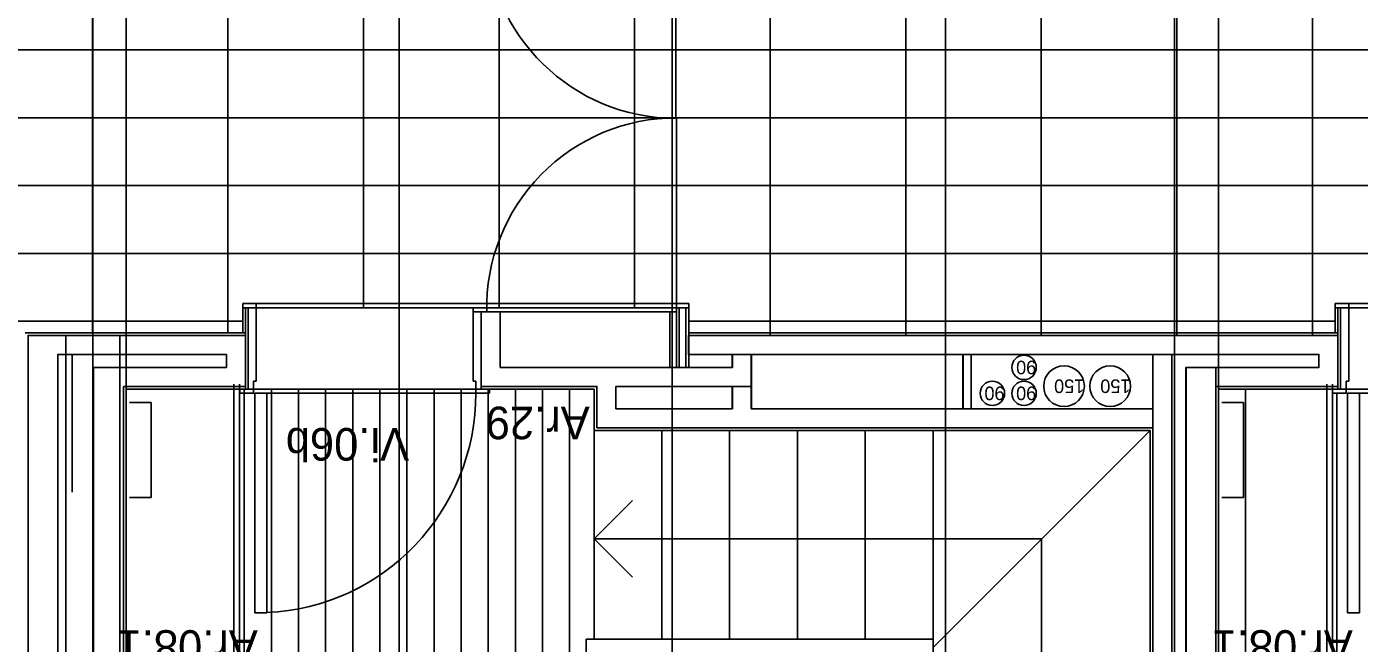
# Model space of a CAD drawing. Extents: x 1248 to 1356, y -443 to -224.
# Drawn here: x 1299.176 to 1304.091, y -239.861 to -237.588 of the extents above; entities that cross this region are included whole.
import ezdxf

# ---------------------------------------------------------------- set-up
doc = ezdxf.new("R2010")
doc.units = 0
for name, color, linetype in [('corte', 7, 'Continuous'), ('estereoctomias', 7, 'Continuous'), ('Level 1', 7, 'Continuous'), ('Level 10', 7, 'Continuous'), ('Level 13', 7, 'Continuous'), ('Level 2', 7, 'Continuous'), ('Level 4', 7, 'Continuous'), ('Level 40', 7, 'Continuous'), ('Level 41', 7, 'Continuous'), ('mob-fixo', 7, 'Continuous'), ('revestimentos', 7, 'Continuous'), ('vermelhos-cont', 7, 'Continuous'), ('vermelhos-tracej', 7, 'Continuous')]:
    doc.layers.add(name, color=color, linetype=linetype)

msp = doc.modelspace()

# ---------------------------------------------------------------- linework, layer by layer
at = {"layer": 'corte'}
for p, q in [((1300.8527, -238.914), (1300.8527, -238.639)), ((1300.9227, -238.844), (1300.9227, -238.639)), ((1299.3208, -238.7263), (1299.519, -238.7263)), ((1302.629, -238.7963), (1302.629, -238.9963)), ((1302.659, -238.7963), (1302.659, -238.9963)), ((1303.3294, -238.9963), (1303.3294, -238.7963)), ((1303.3994, -242.7713), (1303.3994, -238.7963)), ((1299.4227, -238.844), (1299.4227, -243.794)), ((1300.9227, -238.844), (1301.7783, -238.844)), ((1303.4523, -238.844), (1303.4523, -242.7713)), ((1303.5623, -243.914), (1303.5623, -238.844)), ((1299.5327, -243.914), (1299.5327, -238.914)), ((1300.8527, -238.914), (1301.2787, -238.914)), ((1301.3487, -238.914), (1301.7783, -238.914)), ((1301.3487, -238.9963), (1301.7783, -238.9963)), ((1301.8483, -238.9963), (1303.3294, -238.9963)), ((1301.8483, -238.9963), (1303.2742, -238.9963)), ((1303.3294, -240.6863), (1303.3294, -239.0763))]:
    msp.add_line(p, q, dxfattribs=at)
msp.add_lwpolyline([(1299.519, -238.7263), (1299.519, -243.774), (1299.3208, -243.774), (1299.3208, -238.7263)], dxfattribs=at)
at = {"layer": 'estereoctomias'}
for p, q in [((1300.8227, -238.624), (1300.0227, -238.624)), ((1304.8523, -238.624), (1304.0523, -238.624))]:
    msp.add_line(p, q, dxfattribs=at)
for points in [[(1303.3298, -239.0663), (1301.2791, -239.0663), (1301.2791, -238.914), (1300.8527, -238.914), (1300.8527, -238.639), (1300.9227, -238.639), (1300.9227, -238.844), (1301.7791, -238.844), (1301.7791, -238.7963), (1301.8491, -238.7963), (1301.8491, -238.914), (1301.3491, -238.914), (1301.3491, -238.9963), (1301.7791, -238.9963), (1301.7791, -238.914), (1301.8491, -238.914), (1301.8491, -238.9963), (1302.6298, -238.9963), (1302.6298, -238.7963), (1302.6598, -238.7963), (1302.6598, -238.9963), (1303.3298, -238.9963)], [(1299.5327, -238.914), (1299.9827, -238.914), (1299.9827, -238.7263), (1299.519, -238.7263), (1299.519, -238.7963), (1299.9127, -238.7963), (1299.9127, -238.844), (1299.519, -238.844), (1299.519, -243.774), (1299.4227, -243.774), (1299.4227, -243.804), (1299.2908, -243.804), (1299.2908, -238.7963), (1299.3208, -238.7963), (1299.3208, -238.7263), (1299.1808, -238.7263), (1299.1808, -243.914), (1299.519, -243.914), (1299.5327, -243.914), (1299.5304, -240.9963), (1299.9404, -240.9963), (1299.9404, -240.9263), (1299.5327, -240.9263)], [(1301.6173, -238.7263), (1301.6173, -238.7963), (1303.9423, -238.7963), (1303.9423, -238.844), (1303.5623, -238.844), (1303.5623, -238.914), (1304.0123, -238.914), (1304.0123, -238.7263)], [(1303.3994, -242.7713), (1303.3294, -242.7713), (1303.3294, -240.7563), (1301.2594, -240.7563), (1301.2594, -240.6863), (1303.3294, -240.6863), (1303.3294, -238.7963), (1303.5738, -238.7963), (1303.3994, -238.7963), (1303.3994, -242.7713)], [(1303.4519, -242.7713), (1303.5619, -242.7713), (1303.5619, -240.9963), (1303.9719, -240.9963), (1303.9719, -240.9263), (1303.5619, -240.9263), (1303.5619, -238.844), (1303.4519, -238.844)]]:
    msp.add_lwpolyline(points, close=True, dxfattribs=at)
at = {"layer": 'Level 1'}
for p, q in [((1300.9227, -238.639), (1300.8527, -238.639)), ((1299.1808, -238.7263), (1299.9827, -238.7263)), ((1299.1808, -243.914), (1299.1808, -238.7263)), ((1299.9827, -238.924), (1299.9827, -238.7163)), ((1301.6177, -238.7263), (1301.6177, -238.7963)), ((1303.5742, -238.7263), (1301.6177, -238.7263)), ((1303.3442, -238.7263), (1304.0123, -238.7263)), ((1304.0123, -238.924), (1304.0123, -238.7163)), ((1299.2908, -238.7963), (1299.9127, -238.7963)), ((1299.2908, -243.794), (1299.2908, -238.7963)), ((1299.3433, -239.304), (1299.3433, -238.7963)), ((1299.9127, -238.844), (1299.9127, -238.7963)), ((1301.7783, -238.7963), (1301.6177, -238.7963)), ((1301.7783, -238.7963), (1301.7783, -238.844)), ((1301.8483, -238.7963), (1301.8483, -238.9963)), ((1303.3294, -238.7963), (1301.8483, -238.7963)), ((1303.3994, -238.7963), (1303.9423, -238.7963)), ((1303.9423, -238.844), (1303.9423, -238.7963)), ((1299.4227, -238.844), (1299.9127, -238.844)), ((1303.4523, -238.844), (1303.9423, -238.844)), ((1299.5327, -238.914), (1299.9827, -238.914)), ((1301.2787, -238.914), (1301.2787, -239.0663)), ((1301.3487, -238.914), (1301.3487, -238.9963)), ((1301.7783, -238.914), (1301.7783, -238.9963)), ((1303.5623, -238.914), (1304.0123, -238.914)), ((1303.3294, -239.0663), (1301.2787, -239.0663))]:
    msp.add_line(p, q, dxfattribs=at)
at = {"layer": 'Level 10'}
for p, q in [((1299.4183, -237.1163), (1299.4183, -238.7163)), ((1299.9183, -237.1163), (1299.9183, -238.7163)), ((1301.9183, -237.1163), (1301.9183, -238.724)), ((1302.4183, -237.1163), (1302.4183, -238.724)), ((1302.9183, -237.1163), (1302.9183, -238.724)), ((1303.4183, -237.1163), (1303.4183, -238.724)), ((1303.9183, -237.1163), (1303.9183, -238.724)), ((1300.4183, -237.2259), (1300.4183, -238.624)), ((1300.9183, -237.2259), (1300.9183, -238.624)), ((1301.4183, -237.2259), (1301.4183, -238.624)), ((1299.1415, -237.674), (1318.1944, -237.674)), ((1299.1415, -237.924), (1318.1944, -237.924)), ((1299.1415, -238.174), (1318.1944, -238.174)), ((1296.6333, -238.424), (1309.5183, -238.424)), ((1299.1231, -238.674), (1299.9727, -238.674)), ((1301.6177, -238.674), (1304.0023, -238.674)), ((1299.9785, -240.9713), (1299.9785, -238.924)), ((1300.8327, -238.924), (1300.0027, -238.924)), ((1300.0785, -243.574), (1300.0785, -238.924)), ((1300.1785, -243.574), (1300.1785, -238.924)), ((1300.2785, -243.574), (1300.2785, -238.924)), ((1300.3785, -243.574), (1300.3785, -238.924)), ((1300.4785, -243.574), (1300.4785, -238.924)), ((1300.5785, -243.574), (1300.5785, -238.924)), ((1300.6785, -243.574), (1300.6785, -238.924)), ((1300.7785, -243.574), (1300.7785, -238.924)), ((1300.8785, -243.574), (1300.8785, -238.924)), ((1300.9785, -243.574), (1300.9785, -238.924)), ((1301.0785, -243.574), (1301.0785, -238.924)), ((1301.1785, -240.7663), (1301.1785, -238.924)), ((1304.0081, -240.9713), (1304.0081, -238.939)), ((1304.8623, -238.924), (1304.0323, -238.924))]:
    msp.add_line(p, q, dxfattribs=at)
at = {"layer": 'Level 13'}
for p, q in [((1299.9727, -238.609), (1299.9727, -238.7163)), ((1300.0227, -238.609), (1299.9727, -238.609)), ((1299.9727, -238.624), (1300.0227, -238.624)), ((1299.9827, -238.7163), (1299.9827, -238.624)), ((1299.9927, -238.924), (1299.9927, -238.624)), ((1300.0227, -238.624), (1300.0227, -238.609)), ((1300.0227, -238.895), (1300.0227, -238.624)), ((1300.8227, -238.639), (1300.8227, -238.624)), ((1300.8727, -238.624), (1300.8227, -238.624)), ((1300.8227, -238.639), (1300.8227, -238.895)), ((1301.5727, -238.639), (1300.8227, -238.639)), ((1300.8527, -238.924), (1300.8527, -238.639)), ((1301.5727, -238.624), (1300.8627, -238.624)), ((1301.5727, -238.624), (1300.8627, -238.624)), ((1301.5727, -238.624), (1300.8727, -238.624)), ((1300.8727, -238.639), (1300.8727, -238.624)), ((1301.5727, -238.624), (1301.5727, -238.609)), ((1301.5727, -238.609), (1301.6177, -238.609)), ((1301.5727, -238.639), (1301.5727, -238.624)), ((1301.5727, -238.624), (1301.6177, -238.624)), ((1301.5727, -238.844), (1301.5727, -238.624)), ((1301.5827, -238.624), (1301.5827, -238.844)), ((1301.6077, -238.624), (1301.6077, -238.844)), ((1301.6177, -238.624), (1301.6177, -238.609)), ((1301.6177, -238.644), (1301.6177, -238.624)), ((1301.6177, -238.644), (1301.6177, -238.844)), ((1304.0023, -238.609), (1304.0023, -238.7163)), ((1304.0523, -238.609), (1304.0023, -238.609)), ((1304.0023, -238.624), (1304.0523, -238.624)), ((1304.0123, -238.7163), (1304.0123, -238.624)), ((1304.0223, -238.924), (1304.0223, -238.624)), ((1304.0523, -238.624), (1304.0523, -238.609)), ((1304.0523, -238.895), (1304.0523, -238.624)), ((1299.9404, -241.0063), (1299.9404, -238.9056)), ((1299.9604, -241.0063), (1299.9604, -238.9056)), ((1300.0227, -238.895), (1300.0127, -238.895)), ((1300.0127, -238.895), (1300.0127, -238.924)), ((1300.0177, -239.749), (1300.0177, -238.939)), ((1300.0177, -238.939), (1300.0617, -238.939)), ((1300.0617, -238.939), (1300.0617, -239.749)), ((1300.8227, -238.895), (1300.8327, -238.895)), ((1300.8327, -238.895), (1300.8327, -238.924)), ((1303.9719, -240.9163), (1303.9719, -238.9056)), ((1303.9919, -241.0063), (1303.9919, -238.9056)), ((1304.0523, -238.895), (1304.0423, -238.895)), ((1304.0423, -238.895), (1304.0423, -238.924)), ((1304.0473, -239.749), (1304.0473, -238.939)), ((1304.0473, -238.939), (1304.0913, -238.939)), ((1304.0913, -238.939), (1304.0913, -239.749)), ((1300.0617, -239.749), (1300.0177, -239.749)), ((1304.0913, -239.749), (1304.0473, -239.749))]:
    msp.add_line(p, q, dxfattribs=at)
for points in [[(1299.9627, -238.939), (1300.0127, -238.939), (1300.0127, -238.924), (1299.9627, -238.924)], [(1300.8827, -238.939), (1300.8327, -238.939), (1300.8327, -238.924), (1300.8827, -238.924)], [(1303.9923, -238.939), (1304.0423, -238.939), (1304.0423, -238.924), (1303.9923, -238.924)]]:
    msp.add_lwpolyline(points, close=True, dxfattribs=at)
at = {"layer": 'Level 2'}
for p, q in [((1301.2687, -239.0763), (1301.2687, -239.8463)), ((1301.5187, -239.0763), (1301.5187, -239.8463)), ((1301.7687, -239.0763), (1301.7687, -239.8463)), ((1302.0187, -239.0763), (1302.0187, -239.8463)), ((1302.2687, -239.0763), (1302.2687, -239.8463)), ((1302.5194, -239.0763), (1302.5194, -239.8463)), ((1302.5194, -239.8763), (1303.3194, -239.0763)), ((1301.4101, -239.3349), (1301.2687, -239.4763)), ((1302.9194, -239.4763), (1301.2687, -239.4763)), ((1301.4101, -239.6177), (1301.2687, -239.4763)), ((1302.9194, -239.4763), (1302.9194, -240.2763)), ((1302.5194, -239.8463), (1301.2394, -239.8463)), ((1301.2394, -240.6763), (1301.2394, -239.8463)), ((1302.5194, -239.9063), (1302.5194, -239.8463))]:
    msp.add_line(p, q, dxfattribs=at)
at = {"layer": 'Level 4'}
for p, q in [((1301.5704, -237.2259), (1301.5704, -237.9259)), ((1301.5727, -238.624), (1301.5727, -237.924)), ((1300.0227, -238.609), (1301.5727, -238.609)), ((1301.5477, -238.844), (1301.5477, -238.639)), ((1304.0523, -238.609), (1305.6023, -238.609)), ((1300.8327, -238.939), (1300.0617, -238.939)), ((1304.8623, -238.939), (1304.0913, -238.939)), ((1299.5546, -238.974), (1299.6346, -238.974)), ((1299.6346, -239.324), (1299.6346, -238.974)), ((1303.5842, -238.974), (1303.6642, -238.974)), ((1303.6642, -239.324), (1303.6642, -238.974)), ((1299.5546, -239.324), (1299.6346, -239.324)), ((1303.5842, -239.324), (1303.6642, -239.324))]:
    msp.add_line(p, q, dxfattribs=at)
for centre, start, end in [((1301.5704, -237.2259), 181.2279, 270), ((1301.5727, -238.624), 90, 181.2279)]:
    msp.add_arc(centre, 0.7, start, end, dxfattribs=at)
msp.add_ellipse((1300.0267, -238.939), major_axis=(0, -0.81), ratio=0.995105, start_param=0.043492, end_param=1.570796, dxfattribs=at)
at = {"layer": 'Level 41'}
for centre, radius in [((1302.8547, -238.8443), 0.045), ((1303.002, -238.9135), 0.075), ((1303.1722, -238.9135), 0.075), ((1302.7379, -238.9397), 0.045), ((1302.8547, -238.9397), 0.045)]:
    msp.add_circle(centre, radius, dxfattribs=at)
at = {"layer": 'mob-fixo'}
msp.add_line((1303.6719, -238.924), (1303.6719, -240.8913), dxfattribs=at)
at = {"layer": 'revestimentos'}
for p, q in [((1299.1708, -238.7163), (1299.9827, -238.7163)), ((1303.5742, -238.7163), (1301.6177, -238.7163)), ((1303.3442, -238.7163), (1304.0123, -238.7163)), ((1299.5427, -238.924), (1299.9746, -238.924)), ((1299.5427, -240.9163), (1299.5427, -238.924)), ((1300.8827, -238.924), (1301.2687, -238.924)), ((1301.2687, -238.924), (1301.2687, -239.0763)), ((1303.5723, -238.924), (1304.0042, -238.924)), ((1303.5723, -240.9163), (1303.5723, -238.924)), ((1301.2687, -239.0763), (1303.3194, -239.0763)), ((1303.3194, -240.6763), (1303.3194, -239.0763))]:
    msp.add_line(p, q, dxfattribs=at)
at = {"layer": 'vermelhos-cont'}
for p, q in [((1299.4199, -250.7923), (1299.4199, -225.5674)), ((1303.4094, -250.7923), (1303.4094, -229.6087))]:
    msp.add_line(p, q, dxfattribs=at)
at = {"layer": 'vermelhos-tracej'}
for p, q in [((1299.5423, -246.757), (1299.5423, -236.1407)), ((1300.5498, -246.757), (1300.5498, -236.1407)), ((1301.5573, -246.757), (1301.5573, -236.1407)), ((1302.5648, -246.757), (1302.5648, -236.1407)), ((1303.5723, -246.757), (1303.5723, -236.1407))]:
    msp.add_line(p, q, dxfattribs=at)

# ---------------------------------------------------------------- texts
at = {"layer": 'Level 40'}
for s, p in [('Ar.29', (1301.2526, -238.9888)), ('Vi.06b', (1300.5866, -239.0676)), ('Ar.08.1', (1300.0285, -239.8129)), ('Ar.08.1', (1304.0673, -239.8129))]:
    msp.add_text(s, height=0.12, rotation=180, dxfattribs=at).set_placement(p)
at = {"layer": 'Level 41'}
for s, p in [('90', (1302.8997, -238.8193)), ('150', (1303.077, -238.8885)), ('150', (1303.2472, -238.8885)), ('90', (1302.7829, -238.9147)), ('90', (1302.8997, -238.9147))]:
    msp.add_text(s, height=0.05, rotation=180, dxfattribs=at).set_placement(p)

doc.saveas('drawing.dxf')
